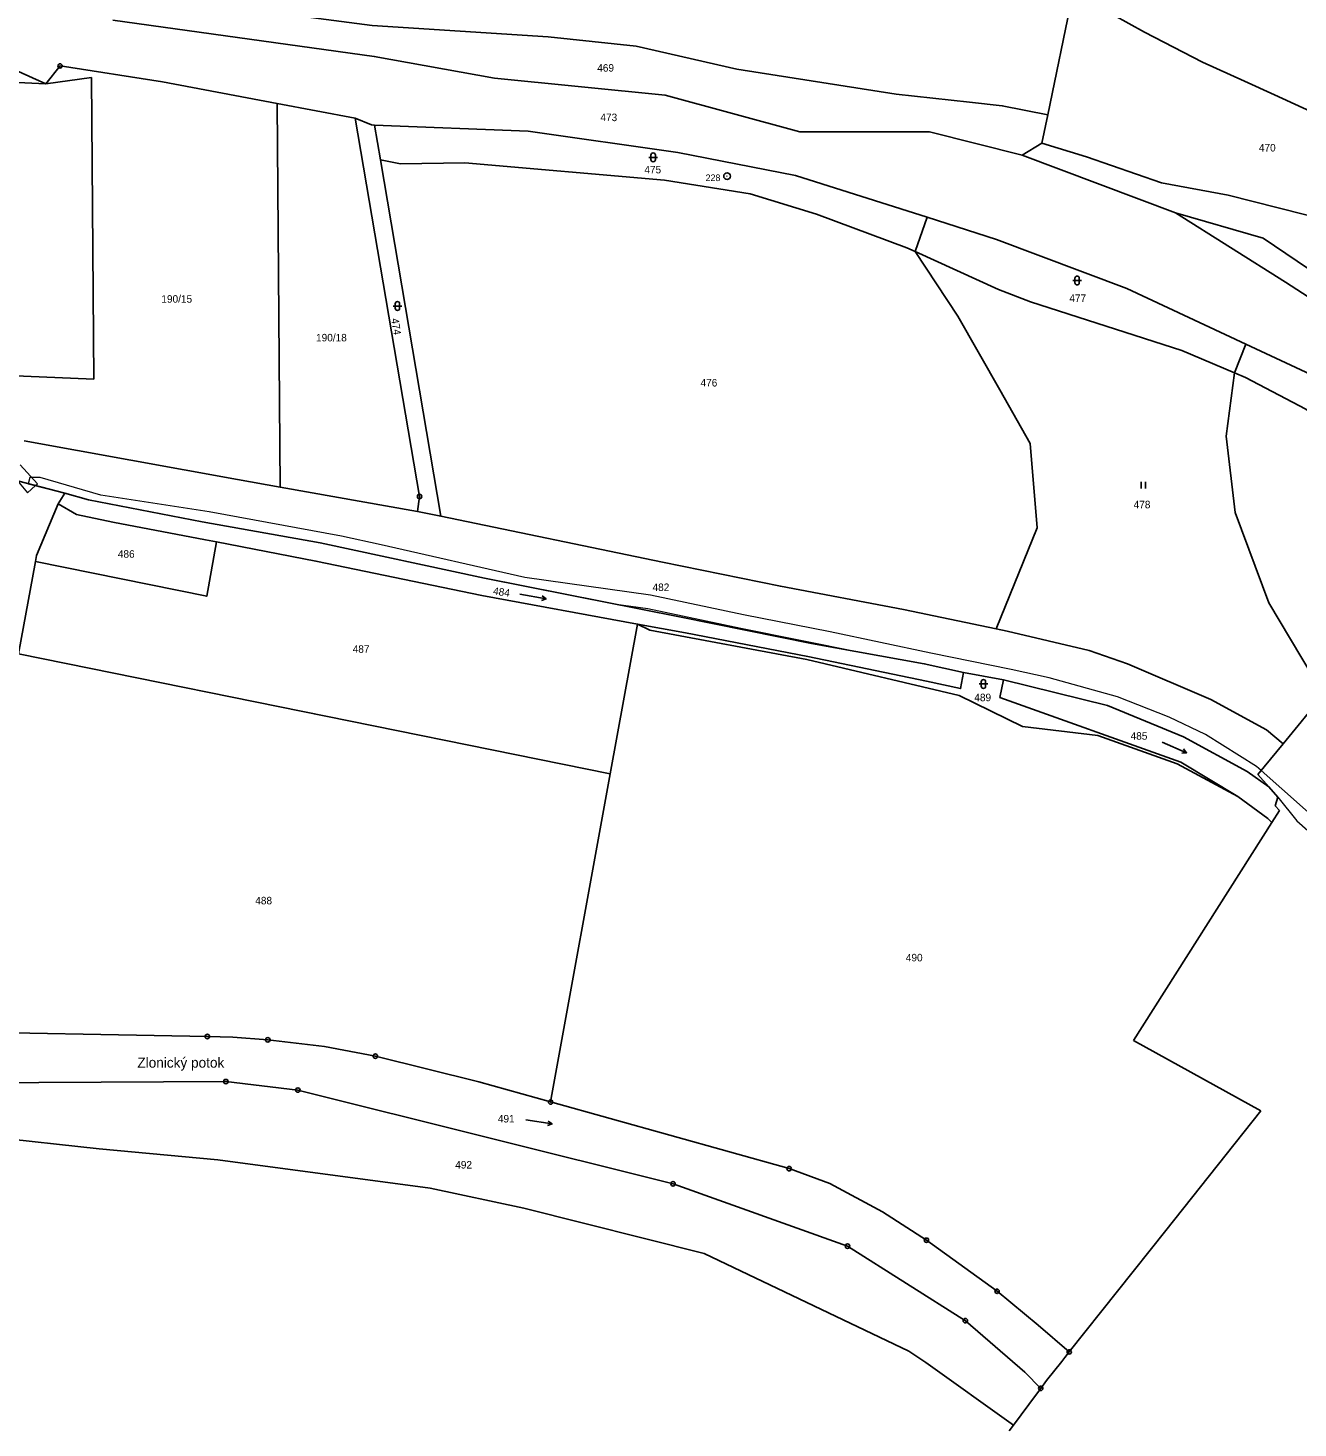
# Model space of a CAD drawing. Extents: x -769392 to -767038, y -1018329 to -1015269.
# Drawn here: x -768267.7 to -767980.5, y -1016508.9 to -1016192.3 of the extents above; entities that cross this region are included whole.
import ezdxf
from ezdxf.enums import TextEntityAlignment as Align

# ---------------------------------------------------------------- set-up
doc = ezdxf.new("R2010")
doc.units = 0
doc.header["$LTSCALE"] = 0.68
for name, color, linetype, lineweight in [('1', 7, 'Continuous', 25), ('13', 7, 'Continuous', 13), ('3', 7, 'Continuous', 25), ('7', 7, 'Continuous', 13), ('8', 7, 'Continuous', 25)]:
    doc.layers.add(name, color=color, linetype=linetype, lineweight=lineweight)
doc.layers.add('2', color=7, linetype='Continuous')

msp = doc.modelspace()

# ---------------------------------------------------------------- linework, layer by layer
at = {"layer": '1'}
for p, q in [((-768029.76, -1016176.15), (-768037.13, -1016211.88)), ((-768263.68, -1016204.89), (-768273.21, -1016204.45)), ((-768263.68, -1016204.89), (-768253.36, -1016203.44)), ((-768253.36, -1016203.44), (-768252.88, -1016271.66)), ((-768237.29, -1016204.43), (-768211.41, -1016209.3)), ((-768211.41, -1016209.3), (-768193.72, -1016212.63)), ((-768211.41, -1016209.3), (-768210.68, -1016296.08)), ((-768037.13, -1016211.88), (-768038.45, -1016218.29)), ((-768189.39, -1016214.21), (-768188.06, -1016222.06)), ((-768042.9, -1016221.04), (-768038.45, -1016218.29)), ((-768008.26, -1016234.04), (-768042.9, -1016221.04)), ((-768188.06, -1016222.06), (-768174.38, -1016302.68)), ((-768064.39, -1016235.08), (-768067.14, -1016242.83)), ((-767994.86, -1016270.26), (-767992.35, -1016263.74)), ((-768272.33, -1016270.82), (-768252.88, -1016271.66)), ((-768220.34, -1016294.37), (-768268.57, -1016285.66)), ((-768210.68, -1016296.08), (-768220.34, -1016294.37)), ((-768259.39, -1016297.5), (-768270.12, -1016294.69)), ((-768259.39, -1016297.5), (-768260.93, -1016299.86)), ((-768179.62, -1016301.59), (-768210.68, -1016296.08)), ((-768174.38, -1016302.68), (-768179.62, -1016301.59)), ((-768266.08, -1016312.93), (-768269.88, -1016333.83)), ((-768136.07, -1016360.95), (-768129.91, -1016327.07)), ((-768136.07, -1016360.95), (-768269.88, -1016333.83)), ((-768056.17, -1016338), (-768047.15, -1016339.71)), ((-767974.79, -1016343), (-767983.92, -1016354.13)), ((-767983.92, -1016354.13), (-767989.64, -1016361.1)), ((-768149.56, -1016435.17), (-768136.07, -1016360.95)), ((-767989.64, -1016361.1), (-767987.15, -1016363.9)), ((-767987.15, -1016363.9), (-767985.06, -1016366.25)), ((-767985.06, -1016366.25), (-767985.68, -1016368.19)), ((-767984.71, -1016369.24), (-767986.43, -1016371.96)), ((-767985.68, -1016368.19), (-767984.71, -1016369.24)), ((-767986.43, -1016371.96), (-768017.7, -1016421.25)), ((-768017.7, -1016421.25), (-767988.94, -1016437.14)), ((-767988.94, -1016437.14), (-768010.4, -1016464.21)), ((-768032.27, -1016491.7), (-768010.4, -1016464.21)), ((-768037.39, -1016498.14), (-768033.98, -1016493.85)), ((-768033.98, -1016493.85), (-768033.25, -1016492.94)), ((-768033.25, -1016492.94), (-768032.27, -1016491.7)), ((-768039.68, -1016501.25), (-768038.72, -1016499.94)), ((-768038.72, -1016499.94), (-768037.39, -1016498.14)), ((-768044.84, -1016508.24), (-768039.68, -1016501.25)), ((-768045.83, -1016509.58), (-768044.84, -1016508.24))]:
    msp.add_line(p, q, dxfattribs=at)
for points in [[(-767911.07, -1016254.35), (-767911.35, -1016254.24), (-767913.83, -1016253.23), (-767922.4, -1016249.43), (-767929.72, -1016245.52), (-767936.18, -1016240.92), (-767940.03, -1016237.62), (-767944.46, -1016232.99), (-767951.01, -1016226.59), (-767958.59, -1016221.19), (-767971.23, -1016214.07), (-767985.88, -1016207.38), (-767992.63, -1016204.28), (-768002.1, -1016199.96), (-768015.26, -1016193.2), (-768022.33, -1016189.3), (-768026.9, -1016184.75), (-768028.26, -1016178.48), (-768028.24, -1016168.79)], [(-768037.13, -1016211.88), (-768047.42, -1016209.86), (-768054.8, -1016209.07), (-768071.38, -1016207.24), (-768107.44, -1016201.58), (-768130.2, -1016196.4), (-768150.13, -1016194.23), (-768189.94, -1016191.66), (-768222.23, -1016187.48), (-768232.37, -1016185.6), (-768239.34, -1016174.56)], [(-768042.9, -1016221.04), (-768063.84, -1016215.78), (-768093.2, -1016215.76), (-768123.63, -1016207.43), (-768162.24, -1016203.59), (-768189.43, -1016198.7), (-768248.53, -1016190.48)], [(-768322.59, -1016194.04), (-768296.98, -1016196.92), (-768276.02, -1016199.42), (-768263.68, -1016204.89)], [(-768263.68, -1016204.89), (-768260.49, -1016200.84), (-768237.29, -1016204.43)], [(-768193.72, -1016212.63), (-768190.04, -1016214.18), (-768189.39, -1016214.21)], [(-768179.62, -1016301.59), (-768179.19, -1016298.22), (-768193.72, -1016212.63)], [(-768189.39, -1016214.21), (-768154.65, -1016215.63), (-768120.8, -1016220.41), (-768094.15, -1016225.62), (-768064.39, -1016235.08)], [(-768038.45, -1016218.29), (-768028.38, -1016221.43), (-768011.42, -1016227.29), (-767996.34, -1016230.05), (-767973.42, -1016235.88), (-767959.11, -1016239.22), (-767944.29, -1016245.02), (-767926.74, -1016256.09), (-767914.88, -1016261.94), (-767914.06, -1016262.5)], [(-768188.06, -1016222.06), (-768183.5, -1016222.98), (-768168.94, -1016222.74), (-768123.78, -1016226.64), (-768104.39, -1016229.8), (-768089.39, -1016234.35), (-768068.96, -1016242), (-768067.14, -1016242.83)], [(-768008.26, -1016234.04), (-767988.38, -1016239.77), (-767921.08, -1016285.34)], [(-767924.32, -1016290.35), (-767942.13, -1016276.4), (-767983.33, -1016249.71), (-768008.26, -1016234.04)], [(-768064.39, -1016235.08), (-768048.71, -1016240.07), (-768019.22, -1016251.2), (-767992.35, -1016263.74)], [(-768067.14, -1016242.83), (-768048.29, -1016251.43), (-768041.05, -1016254.18), (-768006.78, -1016265.17), (-767994.86, -1016270.26)], [(-768067.14, -1016242.83), (-768057.47, -1016257.43), (-768047.96, -1016274.11), (-768041.13, -1016286.25), (-768039.52, -1016305.3), (-768048.83, -1016328.15)], [(-767992.35, -1016263.74), (-767963.08, -1016277.39), (-767936.1, -1016300.15), (-767922.89, -1016312.25), (-767909.74, -1016328.25), (-767894, -1016356.57), (-767878.44, -1016376.56), (-767870.9, -1016394.06), (-767856.61, -1016442.56)], [(-767974.79, -1016343), (-767987.14, -1016322.24), (-767994.73, -1016301.82), (-767996.8, -1016284.58), (-767994.86, -1016270.26)], [(-767994.86, -1016270.26), (-767992.44, -1016271.3), (-767978.79, -1016278.45), (-767963.78, -1016288.55), (-767954.49, -1016296.53), (-767936.21, -1016311.91), (-767919.7, -1016328.71), (-767906.23, -1016347.52), (-767897.29, -1016361.17), (-767889.01, -1016375.92), (-767881.48, -1016390.88), (-767873.96, -1016404.95), (-767866.53, -1016421.37), (-767861.72, -1016433.03), (-767859.65, -1016442.5), (-767859.98, -1016447.38), (-767867.78, -1016462.48), (-767883.19, -1016483.2), (-767887.56, -1016475.7), (-767893.18, -1016466.2), (-767904.81, -1016446.15), (-767913.26, -1016432.32), (-767916.95, -1016428.18)], [(-768056.17, -1016338), (-768065.04, -1016336.04), (-768090.54, -1016331.51), (-768120.43, -1016325.42), (-768164.52, -1016316.68), (-768201.64, -1016308.74), (-768228.35, -1016303.97), (-768254.06, -1016298.95), (-768259.39, -1016297.5)], [(-768260.93, -1016299.86), (-768265.83, -1016311.54), (-768266.08, -1016312.93)], [(-768260.93, -1016299.86), (-768256.8, -1016302.32), (-768248.58, -1016304), (-768227.6, -1016308), (-768225.08, -1016308.49)], [(-768048.83, -1016328.15), (-768069.76, -1016323.78), (-768097.59, -1016318.54), (-768124.25, -1016313.05), (-768174.38, -1016302.68)], [(-768225.08, -1016308.49), (-768227.31, -1016320.78), (-768266.08, -1016312.93)], [(-768225.08, -1016308.49), (-768202.62, -1016312.84), (-768165.12, -1016320.58), (-768129.91, -1016327.07)], [(-767994.17, -1016366.07), (-768007.86, -1016358.68), (-768025.82, -1016352.27), (-768042.83, -1016350.24), (-768057.16, -1016343.25), (-768091.59, -1016335.12), (-768127.11, -1016328.42), (-768129.91, -1016327.07)], [(-768129.91, -1016327.07), (-768119.08, -1016329.06), (-768091.4, -1016334.44), (-768064.55, -1016339.96), (-768056.85, -1016341.68), (-768056.17, -1016338)], [(-767983.92, -1016354.13), (-767987.67, -1016351.02), (-768000.24, -1016344.11), (-768019.1, -1016336.08), (-768027.78, -1016333.05), (-768046.31, -1016328.68), (-768048.83, -1016328.15)], [(-768047.15, -1016339.71), (-768047.94, -1016343.66), (-768007, -1016358.35), (-767994.17, -1016366.07)], [(-768047.15, -1016339.71), (-768023.64, -1016345.48), (-768006.44, -1016352.57), (-767992.04, -1016360.42), (-767987.15, -1016363.9)], [(-767994.17, -1016366.07), (-767987.34, -1016371.09), (-767986.43, -1016371.96)], [(-768149.56, -1016435.17), (-768165.81, -1016430.63), (-768189.18, -1016424.81), (-768200.67, -1016422.65), (-768213.51, -1016421.11), (-768221.38, -1016420.5), (-768227.18, -1016420.37), (-768291.49, -1016419.17)], [(-768038.72, -1016499.94), (-768042.29, -1016496.26), (-768055.76, -1016484.64), (-768082.41, -1016467.78), (-768121.86, -1016453.69), (-768206.72, -1016432.48), (-768223, -1016430.55), (-768293.54, -1016430.88), (-768309.95, -1016431.2)], [(-768032.27, -1016491.7), (-768039.32, -1016485.67), (-768048.59, -1016477.99), (-768064.56, -1016466.44), (-768074.5, -1016460.03), (-768086.43, -1016453.58), (-768095.61, -1016450.25), (-768149.56, -1016435.17)], [(-768301.33, -1016440.37), (-768251.62, -1016445.75), (-768224.79, -1016448.29), (-768176.81, -1016454.69), (-768155.6, -1016459.2), (-768114.8, -1016469.43), (-768068.54, -1016491.55), (-768064.71, -1016494.08), (-768044.84, -1016508.24)]]:
    msp.add_lwpolyline(points, dxfattribs=at)
at = {"layer": '13'}
for points in [[(-768270.12, -1016294.69), (-768266.07, -1016295.75), (-768265.62, -1016295.35), (-768269.5, -1016291.1)], [(-767974.2, -1016373.27), (-767988.9, -1016360.2), (-767989.89, -1016359.33), (-768001.43, -1016352.08), (-768009.66, -1016348.16), (-768021.32, -1016343.54), (-768036.78, -1016339.22), (-768045.42, -1016337.35), (-768063.56, -1016333.65), (-768086.34, -1016328.87), (-768105.92, -1016324.98), (-768126.95, -1016320.52), (-768155.41, -1016316.52), (-768187.87, -1016309.14), (-768196.86, -1016307.19), (-768226.76, -1016301.68), (-768251.25, -1016297.9), (-768265.01, -1016293.9), (-768267.3, -1016293.94), (-768267.67, -1016295.33), (-768259.39, -1016297.5), (-768254.06, -1016298.95), (-768228.35, -1016303.97), (-768201.64, -1016308.74), (-768164.52, -1016316.68), (-768135.23, -1016322.49), (-768127.53, -1016323.57), (-768106.56, -1016328.02), (-768079.58, -1016333.46), (-768065.04, -1016336.04), (-768056.17, -1016338), (-768047.15, -1016339.71), (-768023.64, -1016345.48), (-768006.44, -1016352.57), (-767992.04, -1016360.42), (-767987.15, -1016363.9), (-767985.06, -1016366.25), (-767980.79, -1016371.56), (-767976.4, -1016375.46)]]:
    msp.add_lwpolyline(points, dxfattribs=at)
msp.add_lwpolyline([(-768267.89, -1016297.39), (-768266.07, -1016295.75), (-768270.12, -1016294.69)], close=True, dxfattribs=at)
at = {"layer": '3'}
for p, q in [((-768127.361, -1016221.521), (-768125.359, -1016221.521)), ((-768126.861, -1016221.021), (-768126.861, -1016222.022)), ((-768125.859, -1016222.022), (-768125.859, -1016221.021)), ((-768031.491, -1016249.371), (-768029.489, -1016249.371)), ((-768030.991, -1016248.871), (-768030.991, -1016249.872)), ((-768029.989, -1016249.872), (-768029.989, -1016248.871)), ((-768185.191, -1016255.141), (-768183.189, -1016255.141)), ((-768184.691, -1016254.641), (-768184.691, -1016255.642)), ((-768183.689, -1016255.642), (-768183.689, -1016254.641)), ((-768016.001, -1016296.4), (-768016.001, -1016294.9)), ((-768015, -1016296.4), (-768015, -1016294.9)), ((-768150.58, -1016321.392), (-768151.63, -1016321.716)), ((-768052.671, -1016340.621), (-768050.669, -1016340.621)), ((-768052.171, -1016340.121), (-768052.171, -1016341.122)), ((-768051.169, -1016341.122), (-768051.169, -1016340.121)), ((-768005.716, -1016356.167), (-768006.811, -1016356.247)), ((-768149.211, -1016440.15), (-768150.255, -1016440.493))]:
    msp.add_line(p, q, dxfattribs=at)
for points in [[(-768156.489, -1016320.35), (-768150.58, -1016321.392), (-768151.455, -1016320.729)], [(-768011.239, -1016353.822), (-768005.716, -1016356.167), (-768006.42, -1016355.323)], [(-768155.137, -1016439.212), (-768149.211, -1016440.15), (-768150.098, -1016439.502)]]:
    msp.add_lwpolyline(points, dxfattribs=at)
for centre, start, end in [((-768126.36, -1016221.0209), 0, 180), ((-768126.36, -1016222.0209), 180, 359.98789), ((-768030.49, -1016248.8709), 0, 180), ((-768030.49, -1016249.8709), 180, 359.98789), ((-768184.19, -1016254.6409), 0, 180), ((-768184.19, -1016255.6409), 180, 359.98789), ((-768051.67, -1016340.1209), 0, 180), ((-768051.67, -1016341.1209), 180, 359.98789)]:
    msp.add_arc(centre, 0.5, start, end, dxfattribs=at)
at = {"layer": '8'}
for centre, radius in [((-768260.49, -1016200.8399), 0.5), ((-768260.49, -1016200.8399), 0.0303), ((-768109.66, -1016225.7698), 0.75), ((-768109.66, -1016225.7698), 0.03), ((-768179.19, -1016298.2199), 0.5), ((-768179.19, -1016298.2199), 0.0303), ((-768227.18, -1016420.3699), 0.5), ((-768227.18, -1016420.3699), 0.0303), ((-768213.51, -1016421.1099), 0.5), ((-768213.51, -1016421.1099), 0.0303), ((-768189.18, -1016424.8099), 0.5), ((-768189.18, -1016424.8099), 0.0303), ((-768223, -1016430.5499), 0.5), ((-768223, -1016430.5499), 0.0303), ((-768206.72, -1016432.4799), 0.5), ((-768206.72, -1016432.4799), 0.0303), ((-768149.56, -1016435.1699), 0.5), ((-768149.56, -1016435.1699), 0.0303), ((-768095.61, -1016450.2499), 0.5), ((-768095.61, -1016450.2499), 0.0303), ((-768121.86, -1016453.6899), 0.5), ((-768121.86, -1016453.6899), 0.0303), ((-768082.41, -1016467.7799), 0.5), ((-768082.41, -1016467.7799), 0.0303), ((-768064.56, -1016466.4399), 0.5), ((-768064.56, -1016466.4399), 0.0303), ((-768048.59, -1016477.9899), 0.5), ((-768048.59, -1016477.9899), 0.0303), ((-768055.76, -1016484.6399), 0.5), ((-768055.76, -1016484.6399), 0.0303), ((-768032.27, -1016491.6999), 0.5), ((-768032.27, -1016491.6999), 0.0303), ((-768038.72, -1016499.9399), 0.5), ((-768038.72, -1016499.9399), 0.0303)]:
    msp.add_circle(centre, radius, dxfattribs=at)

# ---------------------------------------------------------------- texts
at = {"layer": '2'}
for s, p in [('469', (-768139.01, -1016202.125)), ('473', (-768138.29, -1016213.325)), ('470', (-767989.38, -1016220.195)), ('475', (-768128.35, -1016225.145)), ('477', (-768032.24, -1016254.205)), ('476', (-768115.65, -1016273.345)), ('478', (-768017.7, -1016300.895)), ('486', (-768247.42, -1016312.075)), ('482', (-768126.5, -1016319.605)), ('487', (-768194.31, -1016333.575)), ('489', (-768053.73, -1016344.525)), ('485', (-768018.39, -1016353.235)), ('488', (-768216.34, -1016390.475)), ('490', (-768069.22, -1016403.365)), ('491', (-768161.48, -1016439.805)), ('492', (-768171.12, -1016450.225))]:
    msp.add_text(s, height=1.7, dxfattribs=at).set_placement(p)
for s, p in [('190/15', (-768234.1, -1016254.395)), ('190/18', (-768199.12, -1016263.145))]:
    msp.add_text(s, height=1.7, dxfattribs=at).set_placement(p, align=Align.CENTER)
for s, rotation, p in [('474', 279, (-768185.609, -1016258.046)), ('484', 352, (-768162.649, -1016320.39))]:
    msp.add_text(s, height=1.7, rotation=rotation, dxfattribs=at).set_placement(p)
at = {"layer": '7'}
msp.add_text('Zlonický potok', height=2.3, dxfattribs=at).set_placement((-768243.01, -1016427.415))
at = {"layer": '8'}
msp.add_text('228', height=1.5, dxfattribs=at).set_placement((-768111.159, -1016226.887), align=Align.RIGHT)

doc.saveas('drawing.dxf')
